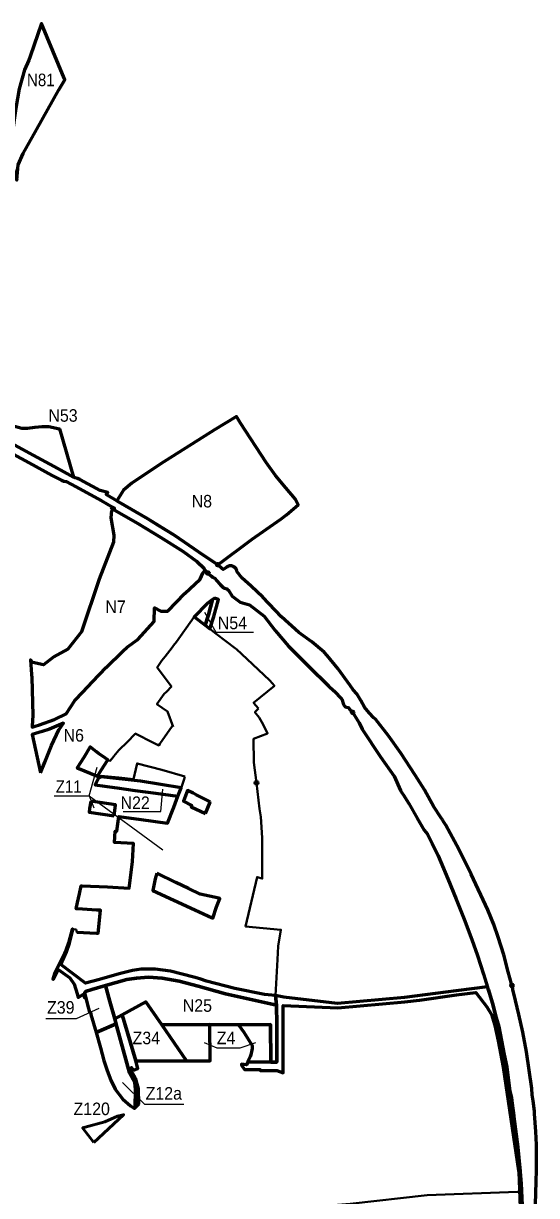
# Model space of a CAD drawing. Extents: x -650277 to -643425, y -1073980 to -1066720.
# Drawn here: x -645952 to -644970, y -1070373 to -1068130 of the extents above; entities that cross this region are included whole.
import ezdxf

# ---------------------------------------------------------------- set-up
doc = ezdxf.new("R2010")
doc.units = 0
doc.header["$LTSCALE"] = 9.6
doc.header["$PDMODE"] = 32
doc.header["$PDSIZE"] = 4.8
for name, color, linetype, lineweight in [('1', 7, 'Continuous', 60), ('11', 7, 'Continuous', 60), ('15', 7, 'Continuous', 60), ('2', 7, 'Continuous', 40), ('3', 7, 'Continuous', 60), ('40', 7, 'Continuous', 60), ('42', 7, 'Continuous', 60), ('48', 7, 'Continuous', 60), ('59', 7, 'Continuous', 25), ('60', 7, 'Continuous', 60), ('63', 7, 'Continuous', 25), ('7', 7, 'Continuous', 60)]:
    doc.layers.add(name, color=color, linetype=linetype, lineweight=lineweight)

msp = doc.modelspace()

# ---------------------------------------------------------------- linework, layer by layer
at = {"layer": '1'}
msp.add_line((-645623.75, -1069825.97), (-645590.964, -1069841.09), dxfattribs=at)
at = {"layer": '1', "lineweight": 40}
msp.add_line((-645726.542, -1069939.398), (-645742.967, -1069941.862), dxfattribs=at)
for points in [[(-645668.722, -1069398.75), (-645696.19, -1069362.01), (-645692.38, -1069356.67), (-645690.81, -1069354.28), (-645687.22, -1069349), (-645680.8, -1069341.08), (-645667, -1069324.06), (-645664.89, -1069320.2), (-645658.9, -1069312.83), (-645625.11, -1069265.42), (-645604.114, -1069281.49), (-645594.94, -1069288.511)], [(-645594.94, -1069288.511), (-645583.13, -1069297.55), (-645546.19, -1069325.81), (-645544.26, -1069327.35), (-645513.41, -1069356.18), (-645480.72, -1069386.96), (-645471.738, -1069397.026), (-645511.464, -1069429.794), (-645501.878, -1069440.838)], [(-645665.58, -1069475.61), (-645675.91, -1069446.56), (-645696.45, -1069432.21), (-645682.28, -1069412.88), (-645678.06, -1069408.54), (-645668.61, -1069398.9), (-645668.722, -1069398.75)], [(-645501.878, -1069440.838), (-645508.994, -1069447.955), (-645501, -1069458), (-645493, -1069471), (-645484.783, -1069488.256), (-645512, -1069499), (-645511, -1069544), (-645506, -1069583)], [(-645786.388, -1069541.673), (-645779.376, -1069532.962), (-645778.754, -1069532.198), (-645769.369, -1069520.672), (-645768.995, -1069520.305), (-645752.715, -1069504.328), (-645738.986, -1069489.868), (-645737.897, -1069488.534), (-645702.82, -1069506.64), (-645692.87, -1069511.229), (-645690.84, -1069508.32), (-645667.31, -1069474.6), (-645665.58, -1069475.61)], [(-645836.44, -1069534.5), (-645824.05, -1069514.34), (-645811.75, -1069523.81), (-645808.1, -1069526.61), (-645799.07, -1069532.8), (-645790.62, -1069538.59), (-645786.388, -1069541.673)], [(-645810.08, -1069570.39), (-645848.78, -1069553.91), (-645836.44, -1069534.5)], [(-645643.16, -1069570.6), (-645687.29, -1069558.04), (-645734.5, -1069545.89), (-645736.8, -1069556.91), (-645741.14, -1069576.19), (-645769.04, -1069573), (-645803.513, -1069569.263), (-645810.08, -1069570.39)], [(-645676.34, -1069660.28), (-645670.23, -1069644.67), (-645664.19, -1069629.24), (-645657.52, -1069612.2), (-645656.15, -1069608.71), (-645649.91, -1069592.39), (-645648.68, -1069589.06), (-645644.56, -1069575.61), (-645643.16, -1069570.6)], [(-645506, -1069583), (-645500.137, -1069632.833), (-645500.137, -1069632.833)], [(-645500.137, -1069632.833), (-645498, -1069648), (-645495, -1069688), (-645495, -1069744), (-645495, -1069766), (-645504.976, -1069763.332), (-645527, -1069858), (-645459.312, -1069864.01), (-645464.288, -1069895.362), (-645465.756, -1069921.035), (-645469.701, -1069990.011)], [(-645839.721, -1069780.247), (-645839.658, -1069779.835), (-645791.2, -1069781.92), (-645749.48, -1069784.61), (-645743.36, -1069733.7), (-645743.01, -1069730.72), (-645741.43, -1069698.68), (-645763.24, -1069697.58), (-645777.62, -1069696.85), (-645776.45, -1069675.26), (-645773.02, -1069675.47), (-645769.36, -1069648), (-645769.264, -1069647.213), (-645726.57, -1069653.22), (-645676.34, -1069660.28)], [(-645804.185, -1069825.84), (-645804.28, -1069826.76), (-645812.18, -1069826.3), (-645847.62, -1069824.26), (-645850.63, -1069824.09), (-645848.35, -1069812.09), (-645844.57, -1069795.07), (-645841.41, -1069779.76), (-645839.658, -1069779.835), (-645839.721, -1069780.247)], [(-645742.967, -1069941.862), (-645768.424, -1069948.431), (-645833, -1069966), (-645880.431, -1069930.3), (-645874.219, -1069917.496), (-645869.262, -1069905.935), (-645863.95, -1069889.468), (-645857.289, -1069863.338), (-645857.204, -1069862.954), (-645850.92, -1069863.41), (-645849.79, -1069868.4), (-645808.84, -1069870.75), (-645808.28, -1069865.39), (-645804.185, -1069825.84)], [(-645469.701, -1069990.011), (-645490.814, -1069988.074), (-645547.4, -1069976.382), (-645614.072, -1069957.797), (-645625.979, -1069954.92), (-645670.325, -1069943.002), (-645699.889, -1069939.714), (-645726.542, -1069939.398)]]:
    msp.add_lwpolyline(points, dxfattribs=at)
at = {"layer": '1'}
for points in [[(-645836.44, -1069534.5), (-645848.78, -1069553.91), (-645810.08, -1069570.39), (-645803.07, -1069558.62), (-645790.62, -1069538.59), (-645799.07, -1069532.8), (-645808.1, -1069526.61), (-645811.75, -1069523.81), (-645824.05, -1069514.34)], [(-645639.638, -1070114.895), (-645594.733, -1070114.868), (-645595.2, -1070045.403), (-645687.31, -1070045.724)], [(-645522.587, -1070116.952), (-645478.664, -1070117.114), (-645479.429, -1070045.409), (-645540.433, -1070045.752), (-645530.3, -1070060.08), (-645514.49, -1070085.4), (-645514.56, -1070090.91), (-645514.61, -1070094.35), (-645517.02, -1070103.08), (-645518.35, -1070106.87), (-645521.73, -1070114.83)]]:
    msp.add_lwpolyline(points, close=True, dxfattribs=at)
for points in [[(-645849.79, -1069868.4), (-645811.848, -1069870.577), (-645808.84, -1069870.75), (-645804.28, -1069826.76), (-645812.18, -1069826.3), (-645847.62, -1069824.26), (-645850.63, -1069824.09), (-645848.35, -1069812.09), (-645844.57, -1069795.07), (-645841.41, -1069779.76), (-645839.658, -1069779.835), (-645791.2, -1069781.92), (-645749.48, -1069784.61), (-645743.36, -1069733.7), (-645741.43, -1069698.68), (-645777.62, -1069696.85), (-645776.45, -1069675.26), (-645773.02, -1069675.47), (-645769.264, -1069647.213), (-645726.57, -1069653.22), (-645676.34, -1069660.28), (-645664.19, -1069629.24), (-645656.15, -1069608.71)], [(-645594.58, -1069619.56), (-645621.56, -1069605.68), (-645626.95, -1069602.91), (-645638.203, -1069597.8), (-645645.715, -1069618.085), (-645629.78, -1069626.03), (-645630.93, -1069628.84), (-645603.7, -1069641.75)], [(-645823.082, -1069618.279), (-645823.13, -1069618.452), (-645825.295, -1069632.053), (-645826.133, -1069638.843), (-645826.151, -1069639.057), (-645778.45, -1069645.92)], [(-645778.45, -1069645.92), (-645775.46, -1069625.13), (-645823.082, -1069618.279)], [(-645603.7, -1069641.75), (-645594.818, -1069620.139), (-645594.58, -1069619.56)], [(-645696.517, -1069756.039), (-645700.028, -1069766.286), (-645704.355, -1069788.786), (-645623.75, -1069825.97)], [(-645578.134, -1069803.73), (-645613.84, -1069795.78), (-645635.79, -1069785.23), (-645660.57, -1069773.31), (-645696.517, -1069756.039)], [(-645590.964, -1069841.09), (-645589.23, -1069841.89), (-645582.31, -1069820.05), (-645577.52, -1069807.26), (-645576.34, -1069804.13), (-645578.134, -1069803.73)], [(-645772.853, -1070049.868), (-645774.423, -1070044.167), (-645783.063, -1070047.855), (-645812.76, -1070060.53)], [(-645737.756, -1070204.389), (-645737.624, -1070169.544), (-645738.79, -1070156.281), (-645748.62, -1070137.889), (-645772.853, -1070049.868)], [(-645812.76, -1070060.53), (-645804.52, -1070089.63), (-645797.66, -1070113.88), (-645791.72, -1070133.09), (-645784.83, -1070151.9), (-645784.83, -1070151.9)], [(-645784.83, -1070151.9), (-645776.26, -1070168.94), (-645761.78, -1070188.29), (-645746.73, -1070201.04), (-645739.12, -1070205.9), (-645737.756, -1070204.389)]]:
    msp.add_lwpolyline(points, dxfattribs=at)
at = {"layer": '1', "lineweight": 53}
msp.add_lwpolyline([(-645816.9, -1070270.96), (-645760.05, -1070217.79), (-645760.91, -1070217.98), (-645772.08, -1070220.39), (-645795.85, -1070231.81), (-645833.92, -1070241.96), (-645838.53, -1070243.19)], close=True, dxfattribs=at)
at = {"layer": '1'}
msp.add_point((-645506, -1069583), dxfattribs=at)
at = {"layer": '11'}
msp.add_lwpolyline([(-645639.638, -1070114.895), (-645687.31, -1070045.724), (-645717.36, -1070002.12), (-645762.868, -1070026.606), (-645757.215, -1070045.97), (-645737.075, -1070114.955)], close=True, dxfattribs=at)
at = {"layer": '15'}
for points in [[(-645586.39, -1069229.32), (-645589.844, -1069231.908), (-645597.738, -1069261.522), (-645604.114, -1069281.49), (-645594.94, -1069288.511), (-645587.298, -1069264.578), (-645578.713, -1069232.375)], [(-645735.532, -1069956.306), (-645712.222, -1069954.725), (-645686.147, -1069956.306), (-645654.145, -1069962.232), (-645617.403, -1069971.714), (-645565.133, -1069986.508), (-645467.472, -1070008.38), (-645469.701, -1069990.011), (-645490.814, -1069988.074), (-645547.4, -1069976.382), (-645601.753, -1069962.317), (-645614.072, -1069957.797), (-645625.979, -1069954.92), (-645670.325, -1069943.002), (-645699.889, -1069939.714), (-645726.542, -1069939.398), (-645742.967, -1069941.862), (-645768.424, -1069948.431), (-645806, -1069959), (-645833, -1069966), (-645880.431, -1069930.3), (-645874.219, -1069917.496), (-645869.262, -1069905.935), (-645863.95, -1069889.468), (-645857.289, -1069863.338), (-645857.204, -1069862.954), (-645858.78, -1069862.84), (-645865.78, -1069888.76), (-645870.89, -1069903.5), (-645876.15, -1069916.47), (-645892.09, -1069947.98), (-645895.66, -1069958.42), (-645894.25, -1069958.7), (-645885.422, -1069940.184), (-645862.782, -1069955.809), (-645854.81, -1069967.927), (-645849.1, -1069986.42), (-645847.135, -1069993.337), (-645836.64, -1069987.18), (-645834.65, -1069994.21), (-645833.32, -1069991.86), (-645835, -1069985), (-645833, -1069982), (-645821, -1069978), (-645794.679, -1069970.596), (-645753.706, -1069959.071)]]:
    msp.add_lwpolyline(points, close=True, dxfattribs=at)
for points in [[(-645061.76, -1069981.21), (-645064.052, -1069973.429), (-645124.233, -1069980.695), (-645222.809, -1069993.701), (-645350.784, -1070005.227), (-645453.852, -1069992.968), (-645469.701, -1069990.011), (-645467.472, -1070008.38), (-645467.068, -1070044.959), (-645466.96, -1070117.157), (-645478.664, -1070117.114), (-645522.587, -1070116.952), (-645524.82, -1070122.48), (-645534.63, -1070121.09), (-645534.7, -1070122.95), (-645529.17, -1070131.4), (-645499.276, -1070131.652), (-645499.142, -1070133.293), (-645466.862, -1070133.219), (-645454.881, -1070137.836), (-645455.073, -1070009.111), (-645350.591, -1070013.242), (-645221.99, -1070001.66), (-645194.003, -1069998.417), (-645123.206, -1069988.629), (-645086.484, -1069984.195), (-645065.235, -1070011.695)], [(-644997.87, -1070391.16), (-644999.47, -1070349.63), (-645001.64, -1070326.4), (-645001.81, -1070324.58), (-645002.308, -1070319.268), (-645005.98, -1070280.14), (-645013.51, -1070222.04), (-645013.77, -1070220.04), (-645016.92, -1070196.32), (-645018.56, -1070184.92), (-645021.14, -1070173.07), (-645027.49, -1070126.56), (-645032.21, -1070102.73), (-645042.27, -1070049.23), (-645047.28, -1070031.83), (-645054.73, -1070004.56), (-645060.612, -1069985.022), (-645061.76, -1069981.21)], [(-645065.235, -1070011.695), (-645056.555, -1070026.163), (-645050.293, -1070047.035), (-645043.92, -1070076.344), (-645034.122, -1070126.616), (-645004.791, -1070324.889), (-645004.523, -1070326.697)], [(-645757.215, -1070045.97), (-645762.868, -1070026.606), (-645777.143, -1070034.287), (-645772.853, -1070049.868), (-645748.62, -1070137.889)], [(-645737.63, -1070147.39), (-645747.67, -1070129.14), (-645745.29, -1070127.83), (-645744.73, -1070129), (-645743.87, -1070130.15), (-645742.67, -1070131.07), (-645741.83, -1070131.53), (-645740.89, -1070131.8), (-645739.41, -1070131.93), (-645738.41, -1070131.78), (-645737.48, -1070131.45), (-645734.77, -1070130.18), (-645732.91, -1070129.5), (-645737.075, -1070114.955), (-645757.215, -1070045.97)], [(-645748.62, -1070137.889), (-645738.79, -1070156.281), (-645737.624, -1070169.544), (-645737.756, -1070204.389)], [(-645737.756, -1070204.389), (-645731.3, -1070197.24), (-645731.94, -1070167.87), (-645737.63, -1070147.39)], [(-645004.523, -1070326.697), (-645004.434, -1070327.302), (-645001.312, -1070412.099), (-645004.327, -1070461.264), (-645014.277, -1070543.11), (-645023.048, -1070595.033), (-645039.574, -1070675.065)]]:
    msp.add_lwpolyline(points, dxfattribs=at)
at = {"layer": '2'}
msp.add_lwpolyline([(-645023.048, -1070595.033), (-645014.277, -1070543.11), (-645004.327, -1070461.264), (-645001.312, -1070412.099), (-645003.03, -1070365.427), (-645003.102, -1070365.432), (-645006.86, -1070365.38), (-645179.26, -1070371.74), (-645326.62, -1070388.32), (-645414.65, -1070395.37), (-645409.38, -1070411.41), (-645408.66, -1070414.62), (-645404.34, -1070433.93), (-645404.4, -1070435.88), (-645440.61, -1070469.53), (-645451.226, -1070466.394), (-645455.09, -1070479.21), (-645458.46, -1070478.86), (-645454.02, -1070501.52), (-645448.36, -1070563), (-645449.82, -1070592.72), (-645442.834, -1070659.455)], dxfattribs=at)
at = {"layer": '3'}
for points in [[(-645794.679, -1069970.596), (-645821, -1069978), (-645833, -1069982), (-645835, -1069985), (-645833.32, -1069991.86)], [(-645833.32, -1069991.86), (-645828.9, -1070007.76), (-645825.08, -1070021.52)], [(-645777.143, -1070034.287), (-645786.238, -1070001.251), (-645794.679, -1069970.596)], [(-645825.08, -1070021.52), (-645823.76, -1070021.67), (-645822.549, -1070025.948), (-645812.76, -1070060.53), (-645783.063, -1070047.855), (-645774.423, -1070044.167), (-645777.143, -1070034.287)]]:
    msp.add_lwpolyline(points, dxfattribs=at)
at = {"layer": '40'}
for points in [[(-645698.83, -1069602.85), (-645656.15, -1069608.71), (-645649.91, -1069592.39), (-645727.71, -1069579.61), (-645803.33, -1069571.62), (-645808.18, -1069573.7), (-645814.82, -1069586.81), (-645777.26, -1069592.07), (-645772.58, -1069592.73), (-645738.13, -1069597.46)], [(-645595.2, -1070045.403), (-645479.429, -1070045.409), (-645478.664, -1070117.114), (-645466.96, -1070117.157), (-645467.068, -1070044.959), (-645467.472, -1070008.38), (-645565.133, -1069986.508), (-645617.403, -1069971.714), (-645654.145, -1069962.232), (-645686.147, -1069956.306), (-645712.222, -1069954.725), (-645735.532, -1069956.306), (-645753.706, -1069959.071), (-645794.679, -1069970.596), (-645786.238, -1070001.251), (-645777.143, -1070034.287), (-645762.868, -1070026.606), (-645717.36, -1070002.12), (-645687.31, -1070045.724)]]:
    msp.add_lwpolyline(points, close=True, dxfattribs=at)
at = {"layer": '42'}
for points in [[(-645856.26, -1068997.79), (-645892.77, -1068977.86), (-645933.28, -1068955.74), (-645975.31, -1068932.8), (-646017.55, -1068909.75)], [(-645973.36, -1068898.93), (-645954.59, -1068904.41), (-645944.23, -1068904.13), (-645930.1, -1068902.47), (-645915.61, -1068901.02), (-645902.91, -1068901.43), (-645882.63, -1068905.88), (-645856.26, -1068997.79)]]:
    msp.add_lwpolyline(points, dxfattribs=at)
msp.add_lwpolyline([(-645604.114, -1069281.49), (-645597.738, -1069261.522), (-645589.844, -1069231.908), (-645600.55, -1069239.93), (-645625.11, -1069265.42)], close=True, dxfattribs=at)
at = {"layer": '48'}
msp.add_lwpolyline([(-645874.15, -1068234.44), (-645917.44, -1068129.99), (-645938.87, -1068193.06), (-645941.41, -1068200.54), (-645949.52, -1068218.72), (-645959.76, -1068255.23), (-645966.56, -1068292.38), (-645973.25, -1068342.08), (-645976.63, -1068393.14), (-645971.94, -1068405.38), (-645964.53, -1068429.83), (-645963.12, -1068415.21), (-645961.7, -1068400.54), (-645952.21, -1068378.95), (-645926.06, -1068332.18), (-645883.87, -1068256.88), (-645880.28, -1068250.47), (-645872.64, -1068238.08)], close=True, dxfattribs=at)
at = {"layer": '59'}
msp.add_lwpolyline([(-645762, -1070156), (-645720, -1070198), (-645645, -1070198)], dxfattribs=at)
at = {"layer": '60'}
for points in [[(-645579.94, -1069165.52), (-645616.63, -1069140.8), (-645662.44, -1069109.89), (-645713.61, -1069078.06), (-645770.04, -1069045.34), (-645773.38, -1069043.46), (-645793.638, -1069031.021), (-645790.53, -1069027.19), (-645805.16, -1069023.52), (-645843.56, -1069002.41), (-645848.18, -1069000.48), (-645852.91, -1068999.62), (-645856.26, -1068997.79), (-645892.77, -1068977.86), (-645933.28, -1068955.74), (-645975.31, -1068932.8)], [(-645993.5, -1068942.1), (-645940.77, -1068970.74), (-645896.91, -1068994.75), (-645879.17, -1069004.02), (-645874.49, -1069005.73), (-645869.83, -1069006.45), (-645850.79, -1069016.84), (-645803.29, -1069042.92), (-645781.12, -1069055.29), (-645777.73, -1069057.2), (-645779.49, -1069059.92), (-645773.29, -1069063.99), (-645732.65, -1069086.82), (-645688.87, -1069113.44), (-645646.08, -1069140.37), (-645620.2, -1069159.26), (-645606.11, -1069172.98), (-645603.91, -1069176.86), (-645599, -1069181.48)], [(-645599, -1069181.48), (-645599, -1069181.48), (-645592.24, -1069187.73), (-645590.41, -1069189.45), (-645584.73, -1069191.88), (-645582.63, -1069195.88), (-645575.58, -1069203.57), (-645568.9, -1069209.87), (-645567.07, -1069210.45), (-645562.17, -1069212.02), (-645560.72, -1069214.25), (-645559.33, -1069214.54), (-645552.2, -1069225.59), (-645537.44, -1069237.41), (-645519.59, -1069242.38), (-645491.63, -1069264.25), (-645470.44, -1069291.24), (-645444.62, -1069321.35), (-645405.7, -1069360.27), (-645368.13, -1069397.37), (-645358.04, -1069406.84), (-645342.49, -1069423.06), (-645339.31, -1069433.27), (-645336.66, -1069437.47), (-645330.57, -1069438.89), (-645327.2, -1069442.53), (-645323.36, -1069445.79), (-645322.13, -1069447.96)], [(-645571.9, -1069173.43), (-645579.94, -1069165.52), (-645579.94, -1069165.52)], [(-645543.43, -1069178.39), (-645543.547, -1069177.727), (-645543.706, -1069177.053), (-645543.907, -1069176.37), (-645544.154, -1069175.682), (-645544.448, -1069174.993), (-645544.792, -1069174.308), (-645545.186, -1069173.63), (-645545.631, -1069172.966), (-645546.127, -1069172.32), (-645546.674, -1069171.699), (-645547.269, -1069171.107), (-645547.91, -1069170.551), (-645548.594, -1069170.034), (-645549.317, -1069169.563), (-645550.076, -1069169.141), (-645550.863, -1069168.772), (-645551.674, -1069168.459), (-645552.504, -1069168.203), (-645553.344, -1069168.007), (-645554.191, -1069167.87), (-645555.036, -1069167.793), (-645555.875, -1069167.772), (-645556.702, -1069167.808), (-645557.511, -1069167.896), (-645558.298, -1069168.035), (-645559.06, -1069168.219), (-645559.793, -1069168.445), (-645560.494, -1069168.709), (-645561.162, -1069169.007), (-645561.794, -1069169.334), (-645562.39, -1069169.686), (-645562.95, -1069170.06), (-645567.5, -1069173.46), (-645569.81, -1069175.03), (-645571.9, -1069173.43)], [(-645017.46, -1069970.61), (-645018.28, -1069967.49), (-645024.45, -1069944.43), (-645032.85, -1069912.07), (-645043.5, -1069878.37), (-645051.78, -1069854.2), (-645063.26, -1069825.99), (-645095.1, -1069757.62), (-645118.98, -1069710.08), (-645143.56, -1069664.05), (-645148.8, -1069656.1), (-645150.3, -1069653.84), (-645153.33, -1069649.24), (-645166.67, -1069629), (-645184.88, -1069596.58), (-645202.56, -1069568.23), (-645230.1, -1069525.98), (-645253.4, -1069493.06), (-645278.31, -1069461.33), (-645281.4, -1069458.4), (-645290.5, -1069449.03), (-645299.61, -1069437.97), (-645306.16, -1069425.55), (-645314.14, -1069412.54), (-645321.1, -1069405.21), (-645326.59, -1069396.64), (-645350.63, -1069363.98), (-645371.12, -1069339.47), (-645376.38, -1069332.65), (-645400.07, -1069313.32), (-645424.8, -1069295.24), (-645458.45, -1069265.56), (-645494.13, -1069227.63), (-645515.89, -1069206.66), (-645534.25, -1069190.56), (-645543.43, -1069178.39)], [(-645322.13, -1069447.96), (-645309.62, -1069467.79), (-645303.57, -1069480.49), (-645268.57, -1069533.23), (-645242.75, -1069570.26), (-645230.42, -1069597.39), (-645227.27, -1069602.68), (-645225.7, -1069605.32), (-645214.76, -1069622.37), (-645198.41, -1069650.49), (-645185.17, -1069673.38), (-645179.12, -1069681.3), (-645170.3, -1069698.91), (-645158.43, -1069722.61), (-645153.44, -1069734.71), (-645140.27, -1069766.68), (-645123.84, -1069805.38), (-645108.74, -1069843.58), (-645094.42, -1069882.65), (-645083.31, -1069913.37), (-645071.53, -1069948.89), (-645063.96, -1069973.73), (-645063.23, -1069976.2), (-645062.57, -1069978.46)], [(-645062.57, -1069978.46), (-645061.76, -1069981.21), (-645060.612, -1069985.022), (-645054.73, -1070004.56), (-645047.28, -1070031.83), (-645042.27, -1070049.23), (-645032.21, -1070102.73), (-645027.49, -1070126.56), (-645021.14, -1070173.07), (-645018.56, -1070184.92), (-645016.92, -1070196.32), (-645013.77, -1070220.04), (-645013.51, -1070222.04), (-645005.98, -1070280.14), (-645002.308, -1070319.268), (-645001.81, -1070324.58), (-645001.64, -1070326.4), (-644999.47, -1070349.63), (-644997.87, -1070391.16)], [(-644996.88, -1070059.73), (-645004.02, -1070026.44), (-645010.54, -1069999.3), (-645015.548, -1069978.177), (-645016.01, -1069976.23), (-645016.89, -1069972.82), (-645017.46, -1069970.61)], [(-644972.48, -1070389.15), (-644971.37, -1070345.98), (-644970.61, -1070323.44), (-644970.55, -1070321.56), (-644970.524, -1070315.358), (-644970.36, -1070275.49), (-644971.47, -1070250.14), (-644974, -1070216.2), (-644974.29, -1070213.17), (-644974.49, -1070210.98), (-644976.94, -1070191.41), (-644978.49, -1070180.05), (-644979.57, -1070167.9), (-644984.21, -1070132.81), (-644989.62, -1070097.79), (-644996.88, -1070059.73)]]:
    msp.add_lwpolyline(points, dxfattribs=at)
for p in [(-645599, -1069181.48), (-645579.94, -1069165.52), (-645322.13, -1069447.96), (-645017.46, -1069970.61)]:
    msp.add_point(p, dxfattribs=at)
at = {"layer": '63'}
for q in [(-645817, -1069631), (-645685, -1069711)]:
    msp.add_line((-645826, -1069608), q, dxfattribs=at)
for points in [[(-645512, -1069295), (-645583, -1069295), (-645605, -1069257)], [(-645893, -1069608), (-645826, -1069608), (-645811, -1069553)], [(-645761, -1069638), (-645689, -1069638), (-645685, -1069595)], [(-645909, -1070034), (-645850, -1070034), (-645806.657, -1070014.297)], [(-645606, -1070080), (-645582, -1070090), (-645537, -1070090), (-645507, -1070080)]]:
    msp.add_lwpolyline(points, dxfattribs=at)
at = {"layer": '7'}
msp.add_line((-645918.82, -1069563.81), (-645910.9, -1069543.64), dxfattribs=at)
for points in [[(-645770.04, -1069045.34), (-645713.61, -1069078.06), (-645694.447, -1069089.98), (-645662.44, -1069109.89), (-645616.63, -1069140.8), (-645579.94, -1069165.52), (-645514.08, -1069116.5), (-645459.5, -1069078.59), (-645448.49, -1069070.45), (-645426.3, -1069051.02), (-645431.85, -1069039.83), (-645449.72, -1069018.58), (-645469.5, -1068995.09), (-645487.38, -1068969.87), (-645536.63, -1068894.79), (-645544.33, -1068882.17), (-645586.28, -1068907.71), (-645690.34, -1068973.16), (-645744.65, -1069009.71), (-645760.07, -1069023.11), (-645773.38, -1069043.46)], [(-645784.69, -1069060.74), (-645783.02, -1069061.84), (-645784.52, -1069075.66), (-645778.75, -1069108.98), (-645779.685, -1069122.296), (-645806.806, -1069193.112), (-645840.644, -1069294.052), (-645867.026, -1069327.317), (-645893.291, -1069341.938), (-645913.23, -1069356.892), (-645933.792, -1069352.53), (-645938.399, -1069347.452), (-645936.046, -1069375.651), (-645935.58, -1069381.24), (-645933.97, -1069453.52), (-645934.8, -1069474.71), (-645935.05, -1069476.32), (-645928.99, -1069474.55), (-645921.13, -1069472.25), (-645892.03, -1069461.43), (-645869.91, -1069451.02), (-645853.28, -1069425.27), (-645838.17, -1069409.28), (-645819.62, -1069389.66), (-645793.63, -1069362.15), (-645761.411, -1069331.17), (-645753.58, -1069323.64), (-645733.1, -1069308.58), (-645701.62, -1069274.36), (-645701.33, -1069247.86), (-645689, -1069254.5), (-645675.82, -1069254.48), (-645643.34, -1069220.59), (-645613.9, -1069193.45), (-645608.71, -1069181.51), (-645603.91, -1069176.86), (-645606.11, -1069172.98), (-645620.2, -1069159.26), (-645646.08, -1069140.37), (-645688.87, -1069113.44), (-645732.65, -1069086.82), (-645773.29, -1069063.99), (-645779.49, -1069059.92), (-645777.73, -1069057.2), (-645781.12, -1069055.29)]]:
    msp.add_lwpolyline(points, close=True, dxfattribs=at)
msp.add_lwpolyline([(-645910.9, -1069543.64), (-645897.92, -1069511.49), (-645884.01, -1069481.56), (-645875.02, -1069468.52), (-645902.19, -1069480.13), (-645916.13, -1069484.55), (-645934.97, -1069490.31), (-645918.82, -1069563.81)], dxfattribs=at)

# ---------------------------------------------------------------- texts
at = {"layer": '1', "width": 0.95}
msp.add_text('Z120', height=24, dxfattribs=at).set_placement((-645855.898, -1070218.668))
at = {"layer": '59', "width": 0.95}
msp.add_text('Z12a', height=24, dxfattribs=at).set_placement((-645718, -1070189))
at = {"layer": '63'}
for s, width, p in [('N81', 0.9, (-645945, -1068250)), ('N53', 0.95, (-645904, -1068892)), ('N8', 0.95, (-645630, -1069056)), ('N7', 0.95, (-645795, -1069258)), ('N54', 0.95, (-645580, -1069289)), ('N6', 0.95, (-645875, -1069504)), ('Z11', 0.9, (-645890, -1069602)), ('N22', 0.95, (-645766, -1069633)), ('Z39', 0.95, (-645906.58, -1070024.53)), ('N25', 0.95, (-645647, -1070021)), ('Z34', 0.95, (-645743, -1070083)), ('Z4', 0.95, (-645582, -1070083))]:
    msp.add_text(s, height=24, dxfattribs=dict(at, width=width)).set_placement(p)

doc.saveas('drawing.dxf')
